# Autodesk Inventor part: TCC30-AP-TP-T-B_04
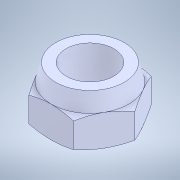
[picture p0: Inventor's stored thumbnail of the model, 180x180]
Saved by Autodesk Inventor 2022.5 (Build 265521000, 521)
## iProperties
Created: 2023-09
Part Number: TCC30-AP-TP-T-B_04
Material: 一般
Document SubType Name: Modeling
Designer: ImaoCorp
Density: 1 g/cm^3
Appearance: 既定
Author: ImaoCorp
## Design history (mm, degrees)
feature "TCC30-AP-TP-T-B_04"
node "ソリッド1"
